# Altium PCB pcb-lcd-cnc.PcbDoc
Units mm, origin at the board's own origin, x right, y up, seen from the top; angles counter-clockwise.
Board outline 96.9 x 63.14 mm, 2 copper layers (Top Layer, Bottom Layer); 18 components, 24 nets, 98 pads, 30 vias.
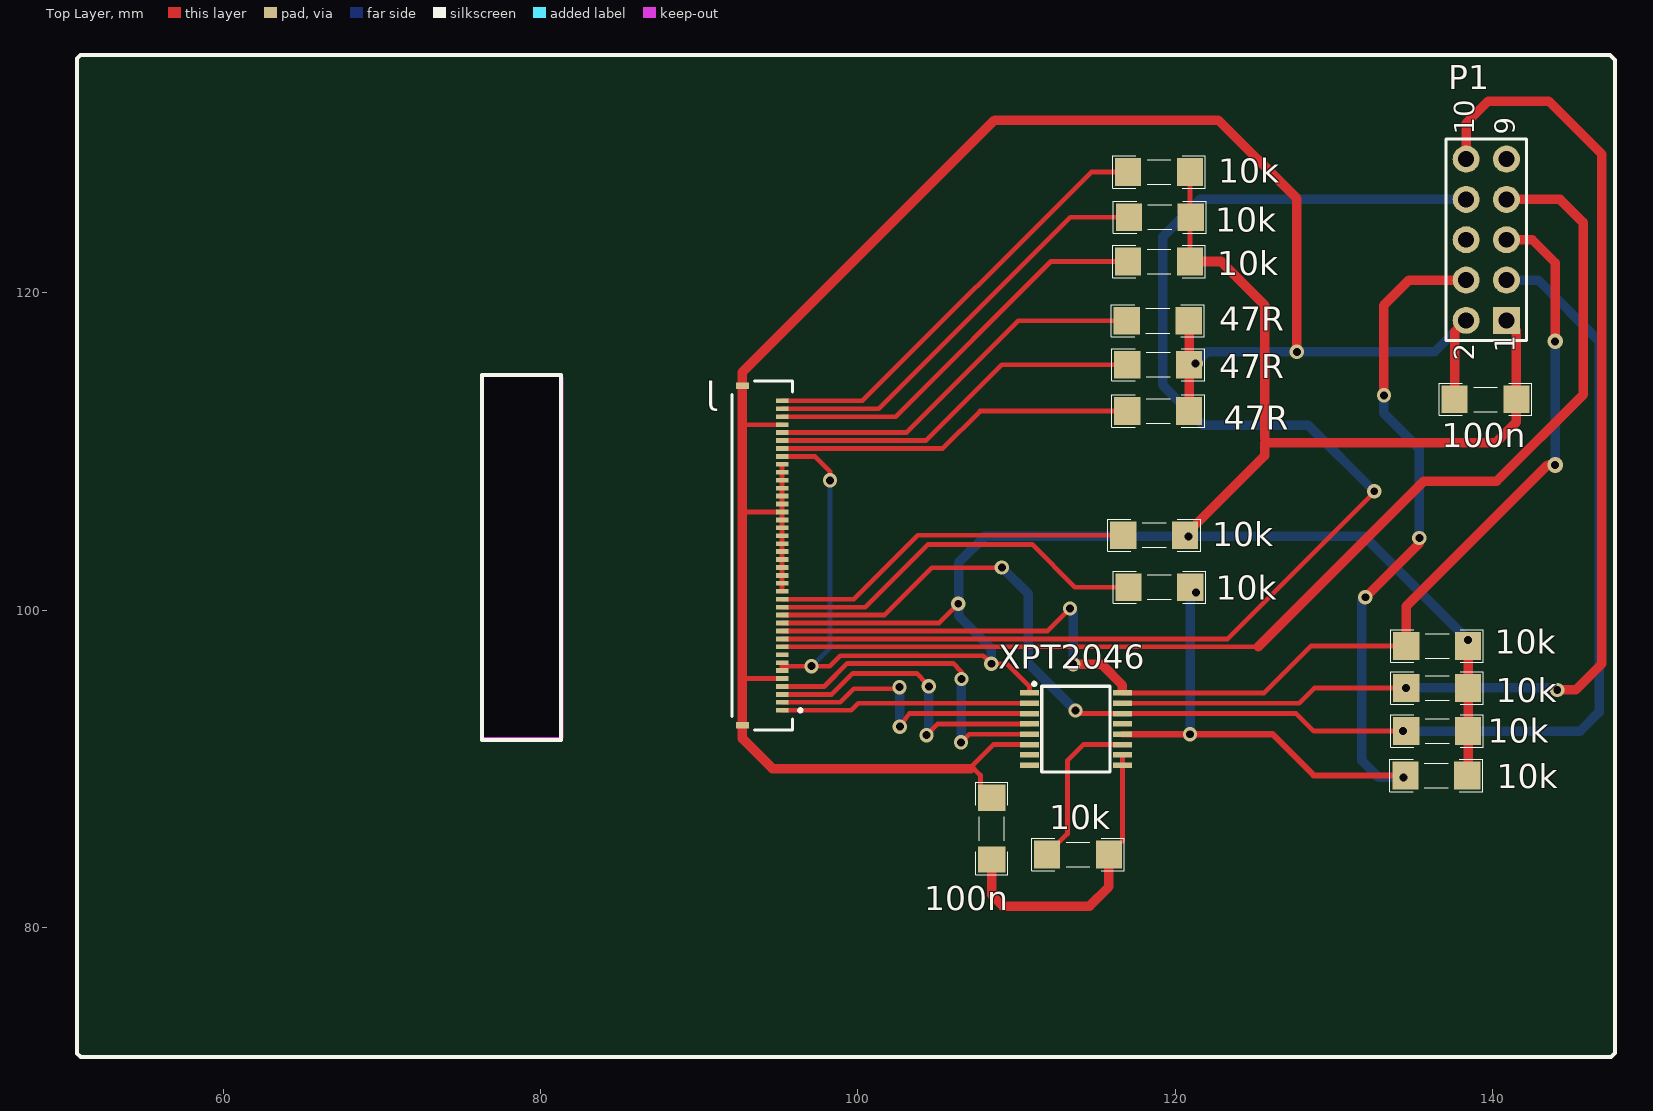
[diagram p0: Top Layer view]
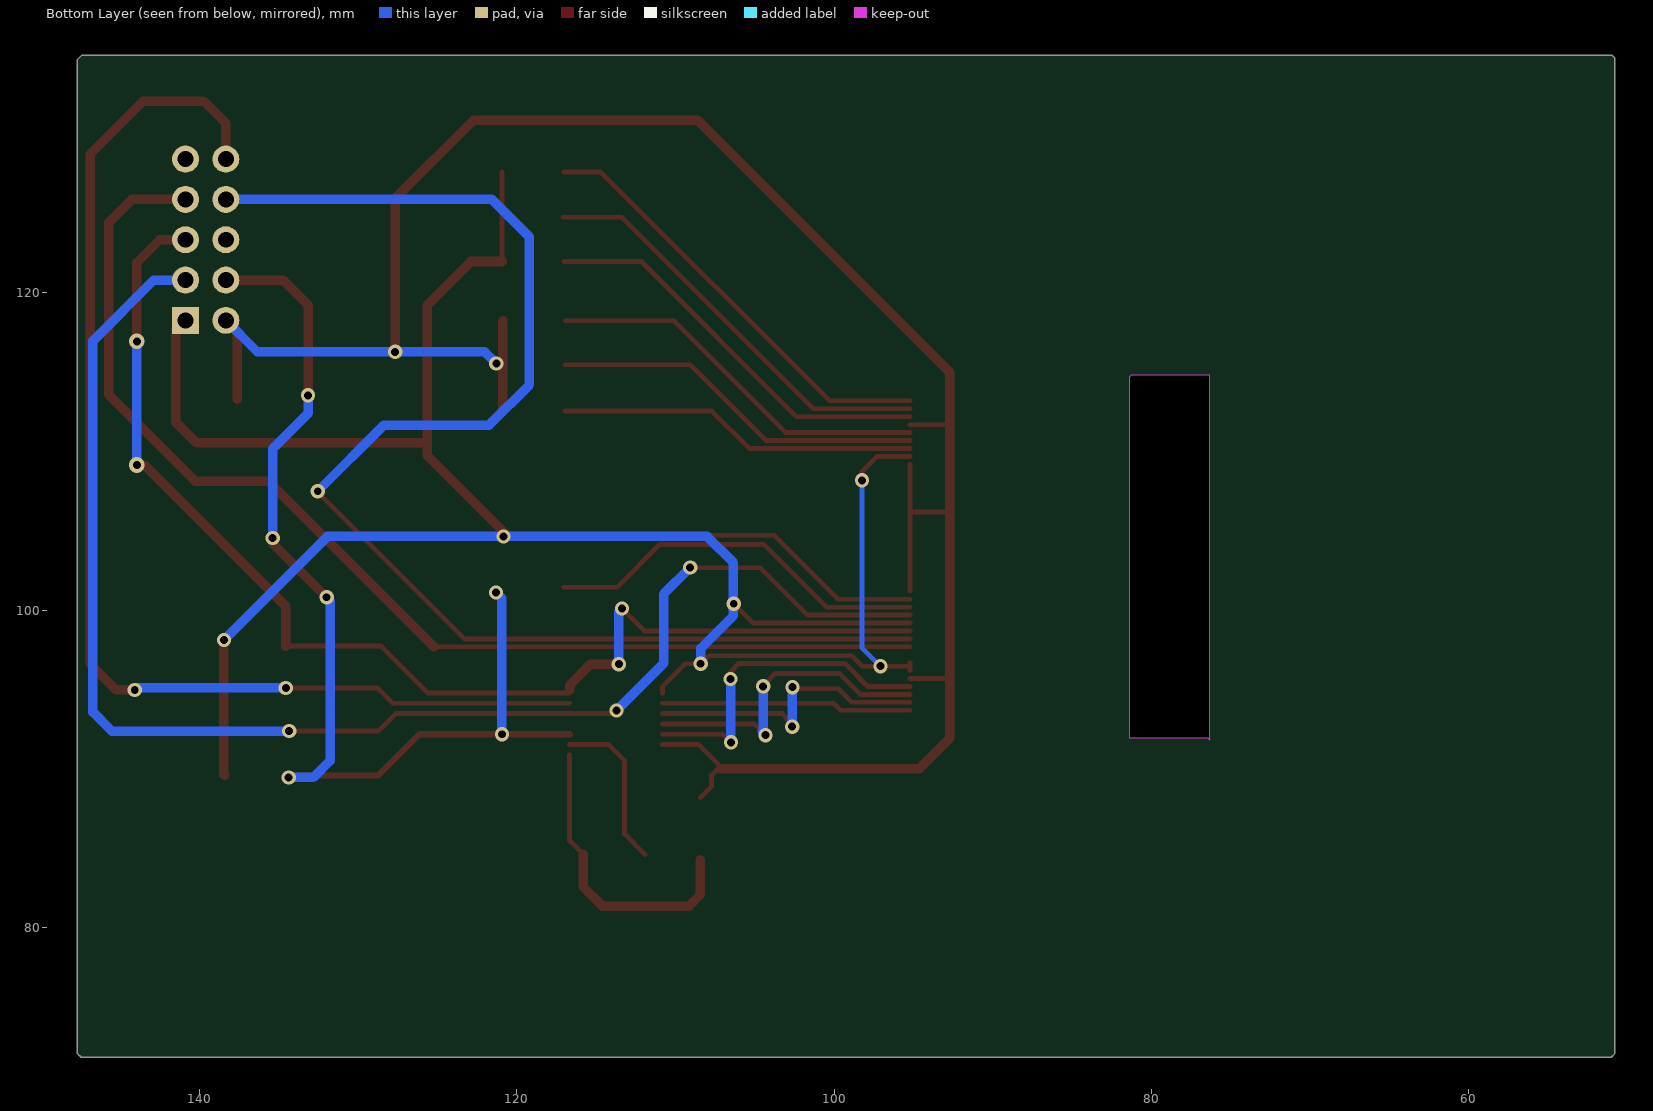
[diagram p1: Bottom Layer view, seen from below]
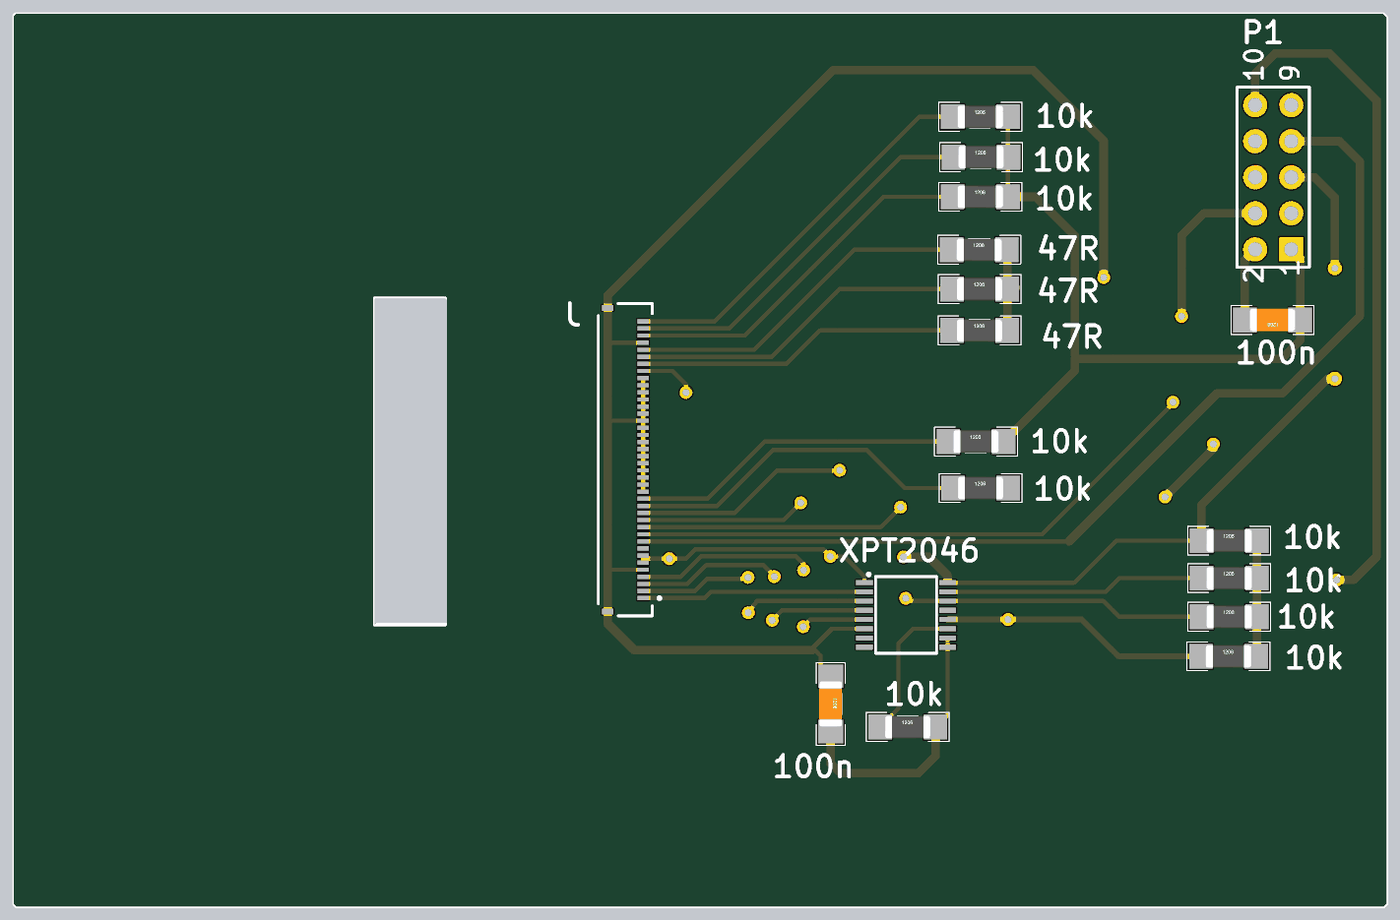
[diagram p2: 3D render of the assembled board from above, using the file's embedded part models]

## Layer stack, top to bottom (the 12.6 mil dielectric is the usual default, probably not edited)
Top Solder: solder mask 0.0102, Solder Resist, Dk 3.5
Top Layer: signal copper 0.0356
Dielectric 1: dielectric 0.32, FR-4, Dk 4.8
Bottom Layer: signal copper 0.0356
Bottom Solder: solder mask 0.0102, Solder Resist, Dk 3.5

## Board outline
51.029,71.831 50.8,72.06 50.8,134.772 51.003,134.976 147.396,134.976 147.701,134.671 147.701,72.085 147.447,71.831
cut-out: 76.327,114.808 81.28,114.808 81.407,114.681 81.407,91.948 76.454,91.948 76.327,91.821

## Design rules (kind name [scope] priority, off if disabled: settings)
Clearance [All] p1: gap=0.1 ignorepadtopadclearanceinfootprint=FALSE
PolygonConnect [All] p1: connectstyle=Relief reliefconductorwidth=0.254 reliefentries=4 polygonreliefangle="90 Angle" airgapwidth=0.254
RoutingVias [All] p1: holewidth=0.711 width=1.27 viastyle="Through Hole" minholewidth=0.711 minwidth=1.27 maxholewidth=0.711 maxwidth=1.27
SolderMaskExpansion [All] p1: expansion=0.102
Width [All] p1: maxlimit=0.6 minlimit=0.2 preferedwidth=0.3
30 further rules are at their usual default settings.

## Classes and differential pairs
component class lcd_pin: 10k 47r 47R 100n IC1 J M? P1 xpt2046

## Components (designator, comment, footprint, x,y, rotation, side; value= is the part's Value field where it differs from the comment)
10k "1K" RESC4817X04N 118.974,127.61 r0 top (schematic designator R13)
10k "1K" RESC4817X04N 119.024,124.765 r0 top (schematic designator R12)
10k "1K" RESC4817X04N 118.974,121.971 r0 top (schematic designator R11)
10k "1K" RESC4817X04N 113.868,84.607 r0 top (schematic designator R7)
10k "1K" RESC4817X04N 136.449,89.586 r0 top (schematic designator R6)
10k "1K" RESC4817X04N 136.5,92.38 r0 top (schematic designator R5)
10k "1K" RESC4817X04N 136.5,95.098 r0 top (schematic designator R4)
10k "1K" RESC4817X04N 136.5,97.739 r0 top (schematic designator R3)
10k "1K" RESC4817X04N 118.669,104.724 r0 top (schematic designator R2)
10k "1K" RESC4817X04N 118.999,101.448 r0 top (schematic designator R1)
47R "1K" RESC4817X04N 118.897,118.237 r0 top (schematic designator R10)
47R "1K" RESC4817X04N 118.923,115.468 r0 top (schematic designator R9)
47R "1K" RESC4817X04N 118.923,112.547 r0 top (schematic designator R8)
100n "0.1uF" CAPC4817X12N 108.433,86.233 r270 top (schematic designator C2)
100n "0.1uF" CAPC4817X12N 139.548,113.284 r180 top (schematic designator C1)
J "FFC2B28-40-G" GCT_FFC2B28-40-G 93.975,103.44 r90 top
P1 "Header 5X2" HDR2X5 140.868,118.262 r90 top
XPT2046 "XPT2046" TSSOP16 113.741,92.507 r0 top (schematic designator IC1)

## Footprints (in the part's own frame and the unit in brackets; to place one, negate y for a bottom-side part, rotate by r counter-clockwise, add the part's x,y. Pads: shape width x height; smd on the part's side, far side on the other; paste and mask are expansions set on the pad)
CAPC4817X12N [mm] "Chip Capacitor, 2-Leads, Body 4/80x1/70mm, IPC Medium Density-Design:Abbas Basereh"
  rect 1.65x1.75 smd: 1(-1.95,0) 2(1.95,0)
  silkscreen extent -2.92,-1.02 2.92,1.02, body extent -1.6,-0.8 1.6,0.8, height 1
GCT_FFC2B28-40-G [mm]
  rect 0.3x0.8 smd: 1(-9.75,-1.25) 2(-9.25,-1.25) 3(-8.75,-1.25) 4(-8.25,-1.25) 5(-7.75,-1.25) 6(-7.25,-1.25) 7(-6.75,-1.25) 8(-6.25,-1.25) 9(-5.75,-1.25) 10(-5.25,-1.25) 11(-4.75,-1.25) 12(-4.25,-1.25) 13(-3.75,-1.25) 14(-3.25,-1.25) 15(-2.75,-1.25) 16(-2.25,-1.25) 17(-1.75,-1.25) 18(-1.25,-1.25) 19(-0.75,-1.25) 20(-0.25,-1.25) 21(0.25,-1.25) 22(0.75,-1.25) 23(1.25,-1.25) 24(1.75,-1.25) 25(2.25,-1.25) 26(2.75,-1.25) 27(3.25,-1.25) 28(3.75,-1.25) 29(4.25,-1.25) 30(4.75,-1.25) 31(5.25,-1.25) 32(5.75,-1.25) 33(6.25,-1.25) 34(6.75,-1.25) 35(7.25,-1.25) 36(7.75,-1.25) 37(8.25,-1.25) 38(8.75,-1.25) 39(9.25,-1.25) 40(9.75,-1.25)
  rect 0.4x0.8 smd: S1(-10.7,1.25) S2(10.7,1.25)
  silkscreen extent -11,-2.5 11,1.9
HDR2X5 [mm] "Connector; Header; 5x2 Position"
  rect 1.7x1.7 hole 1: 1(0,0)
  round 1.7 hole 1: 2(0,2.54) 3(2.54,0) 4(2.54,2.54) 5(5.08,0) 6(5.08,2.54) 7(7.62,0) 8(7.62,2.54) 9(10.16,0) 10(10.16,2.54)
  silkscreen extent -1.27,-1.27 11.43,3.81
RESC4817X04N [mm] "Chip Resistor, 2-Leads, Body 4/80x1/70mm, IPC Medium Density-Design:Abbas Basereh"
  rect 1.65x1.75 smd: 1(-1.95,0) 2(1.95,0)
  silkscreen extent -2.92,-1.02 2.92,1.02, body extent -1.6,-0.8 1.6,0.8, height 1
TSSOP16 [mm]
  rect 1.2x0.35 smd: 1(-2.925,2.275) 2(-2.925,1.625) 3(-2.925,0.975) 4(-2.925,0.325) 5(-2.925,-0.325) 6(-2.925,-0.975) 7(-2.925,-1.625) 8(-2.925,-2.275) 9(2.925,-2.275) 10(2.925,-1.625) 11(2.925,-0.975) 12(2.925,-0.325) 13(2.925,0.325) 14(2.925,0.975) 15(2.925,1.625) 16(2.925,2.275)
  silkscreen extent -2.72,-2.7 2.15,2.95

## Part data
10k 10k 10k 10k 10k 10k 10k 10k 10k 10k 47R 47R 47R: library part "RES 1206 0.25W", "RES 1206"
100n 100n: library part "CAP SMD 1206", "CAP 1206"
J: "40 Position FFC, FPC Connector Contacts, Top and Bottom 0.020 _0.50mm_ Surface Mount, Right Angle", Package="Package Analog Devices"
P1: "Header, 5-Pin, Dual row"
XPT2046: "RASPBERRY PI 3.5 TFT DISPLAY", Package=Package

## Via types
v1: diameter 0.9, hole 0.5, Top Layer to Bottom Layer, 28 vias
v2: diameter 1, hole 0.5, Top Layer to Bottom Layer, 2 vias

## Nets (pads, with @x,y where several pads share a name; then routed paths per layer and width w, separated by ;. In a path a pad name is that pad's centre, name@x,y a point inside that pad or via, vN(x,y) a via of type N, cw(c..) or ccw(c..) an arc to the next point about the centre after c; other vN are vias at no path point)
cs_lcd: J.9 P1.7 | length 73.3
  Top Layer w0.3: J.9 125.223,97.69
  Top Layer w0.6: 125.223,97.69 135.661,108.128 140.259,108.128 145.694,113.563 145.694,124.435 144.247,125.882 P1.7
cs_touch: 10k.1@134.55,95.098 P1.10 XPT2046.15 | length 76.2
  Top Layer w0.3: XPT2046.15 127.812,94.132 128.778,95.098 v1(134.55,95.098)
  Top Layer w0.6: P1.10 138.328,130.683 139.725,132.08 143.535,132.08 146.888,128.727 146.888,96.622 145.237,94.971 v1(144.069,94.971)
  Bottom Layer w0.6: v1(134.55,95.098) v1@144.069,95.098
GND: 47R.2 100n.1@108.433,88.183 100n.2@137.598,113.284 J.5 J.16 J.17 J.18 J.19 J.20 J.21 J.22 J.23 J.24 J.25 J.26 J.27 J.28 J.29 J.30 J.31 J.32 J.37 J.S1 J.S2 P1.2 XPT2046.6 | length 143.2
  Top Layer w0.2: 92.725,111.582 92.832,111.69
  Top Layer w0.3: 92.725,95.733 92.767,95.69 J.5 ; 92.725,106.147 92.768,106.19 J.26 ; 92.832,111.69 J.37 ; J.16 J.17 J.18 J.19 J.20 J.21 J.22 J.23 J.24 J.25 J.26 ; J.32 J.31 J.30 J.29 J.28 J.27 J.26 ; 100n.1@108.433,88.183 107.721,88.894 107.721,89.611 107.315,90.018 107.01,90.018 108.524,91.532 XPT2046.6
  Top Layer w0.6: 107.112,90.018 94.615,90.018 92.725,91.908 J.S1 92.725,95.733 92.725,106.147 92.725,111.582 J.S2 92.725,115 108.61,130.886 122.707,130.886 127.66,125.933 v1(127.66,116.281) ; 47R.2@120.847,118.237 120.873,118.212 47R.2@120.873,115.545 ; 47R.2@120.873,112.547 47R.2@120.873,115.468 ; 100n.2@137.598,113.284 137.598,117.532 P1.2
  Bottom Layer w0.6: v1(121.285,115.545) 122.022,116.281 v1(127.66,116.281) 136.347,116.281 P1.2
miso: 10k.1@134.499,89.586 10k.2@120.949,101.448 P1.4 XPT2046.12 | length 68.2
  Top Layer w0.3: v1(134.372,89.459) 10k.1@134.499,89.586
  Top Layer w0.4: XPT2046.12 v1(120.929,92.182) 126.131,92.182 128.727,89.586 10k.1@134.499,89.586
  Top Layer w0.6: v1(131.978,100.813) 135.382,104.216 v1(135.382,104.546) ; v1(133.147,113.538) 133.147,119.228 134.722,120.802 P1.4
  Bottom Layer w0.6: v1(120.929,92.182) 120.929,100.736 v1(121.31,101.117) ; v1(131.978,100.813) 131.75,100.584 131.75,90.526 132.817,89.459 v1(134.372,89.459) ; v1(133.147,113.538) 133.147,112.395 135.382,110.16 v1(135.382,104.546)
mosi: 10k.1@134.55,92.38 J.13 P1.3 XPT2046.14 | length 91
  Top Layer w0.3: J.13 101.671,99.69 104.648,102.667 v1@109.017,102.667 ; v1(113.716,93.675) 113.909,93.482 XPT2046.14 127.625,93.482 128.727,92.38 v1(134.341,92.38) 10k.1@134.55,92.38
  Bottom Layer w0.6: v1(109.068,102.692) 110.744,101.016 110.744,96.647 v1(113.716,93.675) ; v1(134.341,92.38) 145.517,92.38 146.71,93.574 146.71,116.967 142.875,120.802 P1.3
NetC2_2: 10k.2@115.818,84.607 100n.2@108.433,84.283 XPT2046.9 XPT2046.10 | length 19.1
  Top Layer w0.3: 10k.2@115.818,84.607 116.666,85.455 XPT2046.9 XPT2046.10
  Top Layer w0.6: 100n.2@108.433,84.283 108.433,82.067 109.144,81.356 114.605,81.356 115.818,82.57 10k.2@115.818,84.607
NetIC1_11: 10k.1@111.918,84.607 XPT2046.11 | length 10.3
  Top Layer w0.3: 10k.1@111.918,84.607 113.208,85.897 113.208,90.526 114.214,91.532 XPT2046.11
NetJ_14: 10k.1@117.049,101.448 J.14 | length 24.6
  Top Layer w0.3: J.14 100.469,100.19 104.419,104.14 110.973,104.14 113.665,101.448 10k.1@117.049,101.448
NetJ_15: 10k.1@116.719,104.724 J.15 | length 23.2
  Top Layer w0.3: J.15 99.75,100.69 103.784,104.724 10k.1@116.719,104.724
NetJ_34: 47R.1@116.973,112.547 J.34 | length 22.7
  Top Layer w0.3: J.34 105.338,110.19 107.696,112.547 47R.1@116.973,112.547
NetJ_35: 47R.1@116.973,115.468 J.35 | length 23.7
  Top Layer w0.3: J.35 104.289,110.69 109.068,115.468 47R.1@116.973,115.468
NetJ_36: 47R.1@116.947,118.237 J.36 | length 24.6
  Top Layer w0.3: J.36 103.062,111.19 110.109,118.237 47R.1@116.947,118.237
NetJ_38: 10k.1@117.024,121.971 J.38 | length 25.9
  Top Layer w0.3: J.38 102.385,112.19 112.166,121.971 10k.1@117.024,121.971
NetJ_39: 10k.1@117.074,124.765 J.39 | length 26.9
  Top Layer w0.3: J.39 101.311,112.69 113.386,124.765 10k.1@117.074,124.765
NetJ_40: 10k.1@117.024,127.61 J.40 | length 27.8
  Top Layer w0.3: J.40 100.287,113.19 114.706,127.61 10k.1@117.024,127.61
NetLabel103: P1.6
NetLabel108: P1.9
rs: J.10 P1.8 | length 86.9
  Top Layer w0.2: v1(132.537,107.493) v1@132.613,107.493
  Top Layer w0.3: J.10 123.31,98.19 v1@132.613,107.493
  Bottom Layer w0.6: v1(132.537,107.493) 128.372,111.658 121.742,111.658 119.202,114.198 119.202,123.52 121.564,125.882 P1.8
sck: 10k.1@134.55,97.739 J.11 P1.5 XPT2046.16 | length 77.6
  Top Layer w0.2: XPT2046.16 116.666,94.971
  Top Layer w0.3: J.11 111.949,98.69 v1(113.36,100.101) ; XPT2046.16 125.592,94.782 128.549,97.739 10k.1@134.55,97.739
  Top Layer w0.6: v1(113.563,96.596) 115.341,96.596 116.666,95.271 116.666,94.971 ; 10k.1@134.55,97.739 134.55,100.234 143.459,109.144 v2(143.942,109.144) ; P1.5 142.494,123.342 143.942,121.895 v2(143.942,116.942)
  Bottom Layer w0.6: v1(113.36,100.101) 113.563,99.898 v1(113.563,96.596) ; v2(143.942,109.144) v2(143.942,116.942)
VCC: 10k.2@120.619,104.724 10k.2@120.924,121.971 10k.2@120.924,127.61 10k.2@120.974,124.765 10k.2@138.45,92.38 10k.2@138.45,95.098 10k.2@138.45,97.739 10k.2@138.399,89.586 100n.1@141.498,113.284 J.6 J.7 J.12 J.33 P1.1 XPT2046.1 | length 147.5
  Top Layer w0.3: J.6 95.225,96.469 ; J.7 95.225,96.469 ; J.12 105.108,99.19 v1(106.324,100.406) ; J.33 97.295,109.69 98.247,108.737 v1(98.247,108.179) ; XPT2046.1 110.816,95.178 109.372,96.622 v1(108.407,96.622) 107.899,97.13 98.882,97.13 98.222,96.469 v1(97.079,96.469) 95.225,96.469 ; 10k.2@120.924,121.971 10k.2@120.924,127.61
  Top Layer w0.6: 10k.2@120.619,104.724 125.628,109.734 125.628,110.541 140.183,110.541 141.498,111.856 141.498,113.284 141.498,117.633 P1.1 ; 10k.2@120.924,121.971 122.885,121.971 125.628,119.228 125.628,110.846 ; 10k.2@138.399,89.586 138.45,89.637 138.45,92.38 138.45,95.098 138.45,97.739 v1(138.45,98.126)
  Bottom Layer w0.3: v1(97.079,96.469) 98.247,97.638 v1(98.247,108.179)
  Bottom Layer w0.6: v1(106.324,100.406) 106.35,100.381 106.35,99.644 108.407,97.587 v1(108.407,96.622) ; v1@106.35,100.406 106.35,102.997 108.001,104.648 v1(120.828,104.648) 131.928,104.648 v1(138.45,98.126)
x+: J.1 XPT2046.2 | length 15.8
  Top Layer w0.3: J.1 99.583,93.69 100.025,94.132 XPT2046.2
x-: J.3 XPT2046.4 | length 19.9
  Top Layer w0.3: J.3 98.347,94.69 99.67,96.012 103.708,96.012 v1@104.318,95.402 ; v1(104.318,92.126) 105.024,92.832 XPT2046.4
  Bottom Layer w0.6: v1(104.318,92.126) 104.521,92.329 104.47,92.38 v1(104.47,95.199)
y+: J.2 XPT2046.3 | length 18.9
  Top Layer w0.3: J.2 98.889,94.19 99.746,95.047 102.387,95.047 102.286,95.148 v1(102.616,95.148) ; v1(102.641,92.659) 103.235,93.482 XPT2046.3
  Bottom Layer w0.6: v1(102.641,92.659) v1@102.641,95.021
y-: J.4 XPT2046.5 | length 21.4
  Top Layer w0.3: J.4 97.882,95.19 99.339,96.647 105.994,96.647 106.528,96.114 v1(106.528,95.656) ; v1(106.502,91.669) 107.015,92.182 XPT2046.5
  Bottom Layer w0.6: v1(106.502,91.669) 106.502,95.783 106.528,95.758 v1(106.528,95.656)
pads on no net: J.8 XPT2046.7 XPT2046.8 XPT2046.13

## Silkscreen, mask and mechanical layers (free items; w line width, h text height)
Top Overlay:
  lines w0.254: 50.8,72.06 50.8,134.772 51.003,134.976 147.396,134.976 147.701,134.671 147.701,72.085 147.447,71.831 51.029,71.831 50.8,72.06 ; 76.327,91.821 76.327,114.808 81.28,114.808 81.28,91.821 76.327,91.821
Mechanical 2:
  lines w0.013: 51.749,72.358 51.749,134.358 146.749,134.358 146.749,72.358 51.749,72.358 ; 76.365,91.834 76.365,114.834 81.365,114.834 81.365,91.834 76.365,91.834 ; 91.634,92.058 91.634,115.058 96.634,115.058 96.634,92.058 91.634,92.058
